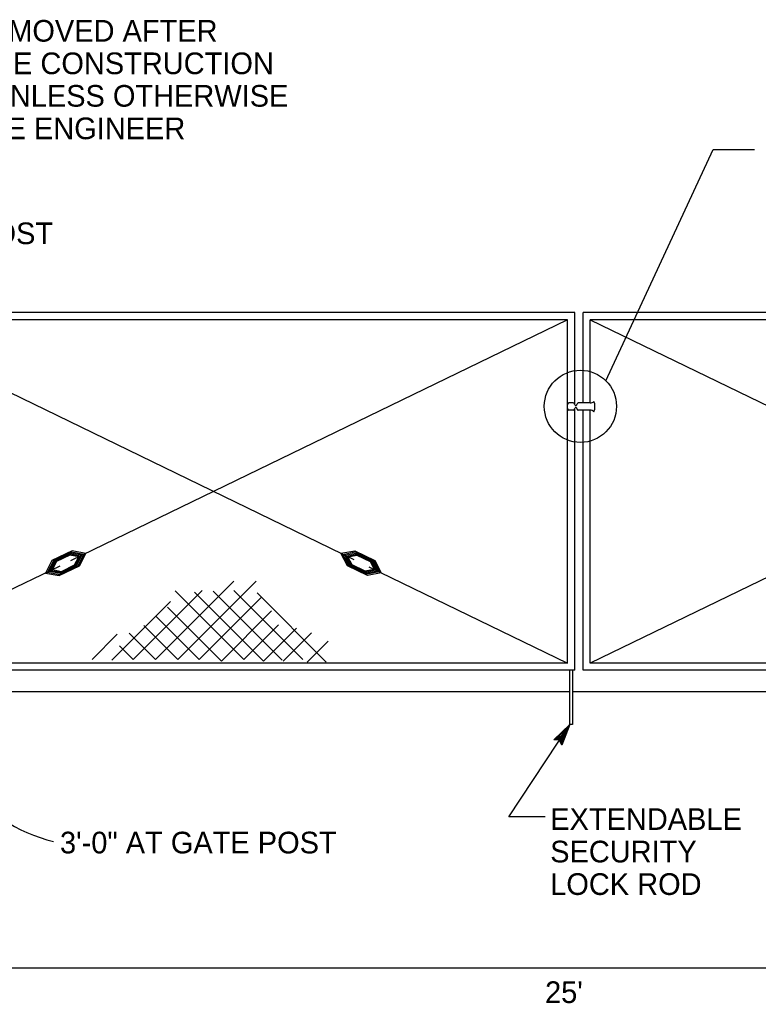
# Model space of a CAD drawing. Extents: x -121875 to -117742, y -103854 to -101122.
# Drawn here: x -121111.6 to -120907.1, y -102467.4 to -102195.2 of the extents above; entities that cross this region are included whole.
import ezdxf

# ---------------------------------------------------------------- set-up
doc = ezdxf.new("R2010")
doc.units = 0
for name, color, linetype in [('G-MARK', 7, 'Continuous'), ('Misc CnstDet(22)', 7, 'Continuous'), ('Nongeo Data(60)', 7, 'Continuous')]:
    doc.layers.add(name, color=color, linetype=linetype)

msp = doc.modelspace()

# ---------------------------------------------------------------- linework, layer by layer
at = {"layer": 'G-MARK'}
for p, q in [((-120919.67, -102231.09), (-120908.16, -102231.09)), ((-120976.24, -102415.84), (-120959.35, -102390.2)), ((-120963.77, -102394.47), (-120959.35, -102390.2)), ((-120959.35, -102390.2), (-120961.54, -102395.94)), ((-120959.35, -102390.2), (-120959.35, -102390.2)), ((-120963.36, -102394.49), (-120960.11, -102391.35)), ((-120962.93, -102394.49), (-120960.87, -102392.51)), ((-120960.87, -102392.51), (-120961.9, -102395.21)), ((-120960.11, -102391.36), (-120961.71, -102395.55)), ((-120962.21, -102394.54), (-120963.77, -102394.47)), ((-120963.77, -102394.47), (-120963.77, -102394.47)), ((-120962.54, -102394.54), (-120961.63, -102393.66)), ((-120961.54, -102395.94), (-120962.21, -102394.54)), ((-120961.63, -102393.66), (-120962.08, -102394.82)), ((-120961.54, -102395.94), (-120961.54, -102395.94)), ((-120966.1, -102415.84), (-120976.24, -102415.84)), ((-121161.89, -102457.55), (-120749.46, -102457.55))]:
    msp.add_line(p, q, dxfattribs=at)
msp.add_lwpolyline([(-120949.32, -102295.1), (-120919.67, -102231.09), (-120919.67, -102231.09)], dxfattribs=at)
msp.add_circle((-120956.39, -102302.17), 10, dxfattribs=at)
msp.add_arc((-121092.33, -102380.7), 43.08, 215.5482, 256.6593, dxfattribs=at)
at = {"layer": 'Misc CnstDet(22)'}
msp.add_lwpolyline([(-120958.59, -102375.24), (-120958.59, -102390.2), (-120959.35, -102390.2), (-120959.35, -102375.24)], dxfattribs=at)
at = {"layer": 'Nongeo Data(60)'}
for p, q in [((-120957.97, -102276.24), (-121157.97, -102276.24)), ((-121155.97, -102278.24), (-121019.1, -102344.59)), ((-120959.97, -102278.24), (-121155.97, -102278.24)), ((-120959.97, -102278.24), (-121097.54, -102344.92)), ((-120959.97, -102301.21), (-120959.97, -102278.24)), ((-120957.97, -102301.58), (-120957.97, -102276.24)), ((-120755.66, -102276.24), (-120955.66, -102276.24)), ((-120955.66, -102301.21), (-120955.66, -102276.24)), ((-120757.66, -102278.24), (-120953.66, -102278.24)), ((-120953.66, -102278.24), (-120816.78, -102344.59)), ((-120953.66, -102301.24), (-120953.66, -102278.24)), ((-120959.97, -102373.24), (-120959.97, -102301.21)), ((-120958.4, -102301.24), (-120959.55, -102301.24)), ((-120957.97, -102301.59), (-120957.97, -102301.58)), ((-120957.97, -102375.24), (-120957.97, -102302.9)), ((-120953.66, -102301.24), (-120957.05, -102301.24)), ((-120955.66, -102301.24), (-120955.66, -102301.21)), ((-120958.4, -102303.24), (-120959.55, -102303.24)), ((-120953.66, -102303.24), (-120957.01, -102303.24)), ((-120955.66, -102375.24), (-120955.66, -102303.24)), ((-120953.66, -102373.24), (-120953.66, -102303.24)), ((-121097.13, -102342.16), (-121102.7, -102344.87)), ((-121097.3, -102342.51), (-121102.32, -102344.94)), ((-121097.47, -102342.82), (-121101.98, -102345.01)), ((-121097.61, -102343.09), (-121101.68, -102345.07)), ((-121097.74, -102343.35), (-121101.4, -102345.12)), ((-121095.25, -102343.82), (-121097.74, -102343.35)), ((-121094.84, -102343.62), (-121097.61, -102343.09)), ((-121094.39, -102343.4), (-121097.47, -102342.82)), ((-121093.89, -102343.16), (-121097.3, -102342.51)), ((-121093.33, -102342.89), (-121097.13, -102342.16)), ((-121096.42, -102346.07), (-121095.25, -102343.82)), ((-121096.14, -102346.12), (-121094.84, -102343.62)), ((-121095.83, -102346.18), (-121094.39, -102343.4)), ((-121095.49, -102346.25), (-121093.89, -102343.16)), ((-121095.1, -102346.32), (-121093.33, -102342.89)), ((-121022.69, -102342.86), (-121018.89, -102342.13)), ((-121020.91, -102346.29), (-121022.69, -102342.86)), ((-121022.13, -102343.14), (-121018.71, -102342.48)), ((-121020.53, -102346.23), (-121022.13, -102343.14)), ((-121021.63, -102343.38), (-121018.55, -102342.8)), ((-121020.19, -102346.17), (-121021.63, -102343.38)), ((-121021.18, -102343.61), (-121018.41, -102343.08)), ((-121019.88, -102346.11), (-121021.18, -102343.61)), ((-121020.77, -102343.81), (-121018.28, -102343.34)), ((-121019.61, -102346.06), (-121020.77, -102343.81)), ((-121018.89, -102342.13), (-121013.32, -102344.85)), ((-121018.71, -102342.48), (-121013.7, -102344.92)), ((-121018.55, -102342.8), (-121014.04, -102344.99)), ((-121018.41, -102343.08), (-121014.35, -102345.06)), ((-121018.28, -102343.34), (-121014.62, -102345.11)), ((-121100.56, -102346.39), (-121155.97, -102373.24)), ((-121102.7, -102344.87), (-121104.48, -102348.31)), ((-121102.32, -102344.94), (-121103.92, -102348.04)), ((-121101.98, -102345.01), (-121103.42, -102347.79)), ((-121101.68, -102345.07), (-121102.97, -102347.57)), ((-121101.4, -102345.12), (-121102.57, -102347.38)), ((-121100.68, -102349.03), (-121095.1, -102346.32)), ((-121100.5, -102348.69), (-121095.49, -102346.25)), ((-121100.35, -102348.38), (-121095.83, -102346.18)), ((-121100.2, -102348.1), (-121096.14, -102346.12)), ((-121100.07, -102347.85), (-121096.42, -102346.07)), ((-121015.34, -102349), (-121020.91, -102346.29)), ((-121015.51, -102348.66), (-121020.53, -102346.23)), ((-121015.67, -102348.36), (-121020.19, -102346.17)), ((-121015.82, -102348.09), (-121019.88, -102346.11)), ((-121015.95, -102347.84), (-121019.61, -102346.06)), ((-121014.93, -102346.61), (-120959.97, -102373.24)), ((-121014.62, -102345.11), (-121013.46, -102347.37)), ((-121014.35, -102345.06), (-121013.05, -102347.56)), ((-121014.04, -102344.99), (-121012.6, -102347.78)), ((-121013.7, -102344.92), (-121012.1, -102348.01)), ((-121013.32, -102344.85), (-121011.54, -102348.28)), ((-120898.24, -102346.39), (-120953.66, -102373.24)), ((-121104.48, -102348.31), (-121100.68, -102349.03)), ((-121103.92, -102348.04), (-121100.5, -102348.69)), ((-121103.42, -102347.79), (-121100.35, -102348.38)), ((-121102.97, -102347.57), (-121100.2, -102348.1)), ((-121102.57, -102347.38), (-121100.07, -102347.85)), ((-121013.46, -102347.37), (-121015.95, -102347.84)), ((-121013.05, -102347.56), (-121015.82, -102348.09)), ((-121012.6, -102347.78), (-121015.67, -102348.36)), ((-121012.1, -102348.01), (-121015.51, -102348.66)), ((-121011.54, -102348.28), (-121015.34, -102349)), ((-121074.05, -102372.23), (-121052.34, -102350.52)), ((-121067.88, -102372.23), (-121046.16, -102350.52)), ((-121080.22, -102372.23), (-121061.12, -102353.13)), ((-121049.61, -102372.23), (-121068.59, -102353.25)), ((-121044.15, -102372.71), (-121063.25, -102353.6)), ((-121038.93, -102372.47), (-121058.03, -102353.36)), ((-121033.23, -102372.23), (-121052.34, -102353.13)), ((-121026.82, -102372.94), (-121045.93, -102353.84)), ((-121086.16, -102372.47), (-121069.9, -102356.21)), ((-121061.95, -102372.23), (-121044.62, -102354.91)), ((-121061.95, -102372.23), (-121073.93, -102360.25)), ((-121055.78, -102372.71), (-121070.73, -102357.76)), ((-121055.78, -102372.71), (-121041.89, -102358.82)), ((-121067.88, -102372.23), (-121077.26, -102362.86)), ((-121049.61, -102372.23), (-121039.99, -102362.62)), ((-121091.61, -102372.23), (-121084.61, -102365.23)), ((-121074.05, -102372.23), (-121081.29, -102364.99)), ((-121044.15, -102372.71), (-121035.01, -102363.57)), ((-121038.69, -102372.71), (-121030.86, -102364.88)), ((-121080.22, -102372.23), (-121084.02, -102368.44)), ((-121032.04, -102372.94), (-121026.23, -102367.13)), ((-120959.97, -102373.24), (-121155.97, -102373.24)), ((-120757.66, -102373.24), (-120953.66, -102373.24)), ((-120957.97, -102375.24), (-121157.97, -102375.24)), ((-120755.66, -102375.24), (-120955.66, -102375.24)), ((-120959.35, -102381.24), (-121161.97, -102381.24)), ((-120955.66, -102381.24), (-120958.59, -102381.24)), ((-120751.66, -102381.24), (-120955.66, -102381.24))]:
    msp.add_line(p, q, dxfattribs=at)
for centre, radius, start, end in [((-120959.54, -102302.79), 0.45, 193.0351, 269.0281), ((-120959.53, -102301.69), 0.45, 90.9719, 166.9649), ((-120958.41, -102301.69), 0.45, 13.0351, 89.0281), ((-120958.41, -102302.79), 0.45, 270.9719, 346.9649), ((-120957.61, -102301.61), 0.368, 177.9728, 273.0727), ((-120957.61, -102302.88), 0.368, 86.9273, 182.0272), ((-120957.8, -102301.46), 0.552, 292.64, 356.8611), ((-120957.8, -102303.02), 0.552, 3.1389, 67.36), ((-120957.02, -102301.47), 0.223, 82.9178, 185.5923), ((-120957.03, -102303.02), 0.223, 174.4077, 277.0822), ((-120953.58, -102300.06), 1.18, 266.4373, 320.9406), ((-120955.95, -102302.25), 3.59, 336.5119, 23.6238), ((-120953.58, -102304.43), 1.18, 39.0594, 93.5627)]:
    msp.add_arc(centre, radius, start, end, dxfattribs=at)

# ---------------------------------------------------------------- texts
at = {"layer": 'Misc CnstDet(22)'}
for s, p in [('BRACE TO BE REMOVED AFTER', (-121182.13, -102201.24)), ('ALL OTHER FENCE CONSTRUCTION', (-121182.13, -102210.24)), ('IS COMPLETED UNLESS OTHERWISE', (-121182.13, -102219.24)), ('DIRECTED BY THE ENGINEER', (-121182.13, -102228.24)), ('GATE POST', (-121148.31, -102257.29)), ('EXTENDABLE', (-120964.75, -102419.41)), ('3\'-0" AT GATE POST', (-121100.48, -102425.92)), ('SECURITY', (-120964.75, -102428.41)), ('LOCK ROD', (-120964.75, -102437.41))]:
    msp.add_text(s, height=6, dxfattribs=at).set_placement(p)
at = {"layer": 'Nongeo Data(60)'}
msp.add_text("25'", height=6, dxfattribs=at).set_placement((-120966.18, -102467.33))

doc.saveas('drawing.dxf')
